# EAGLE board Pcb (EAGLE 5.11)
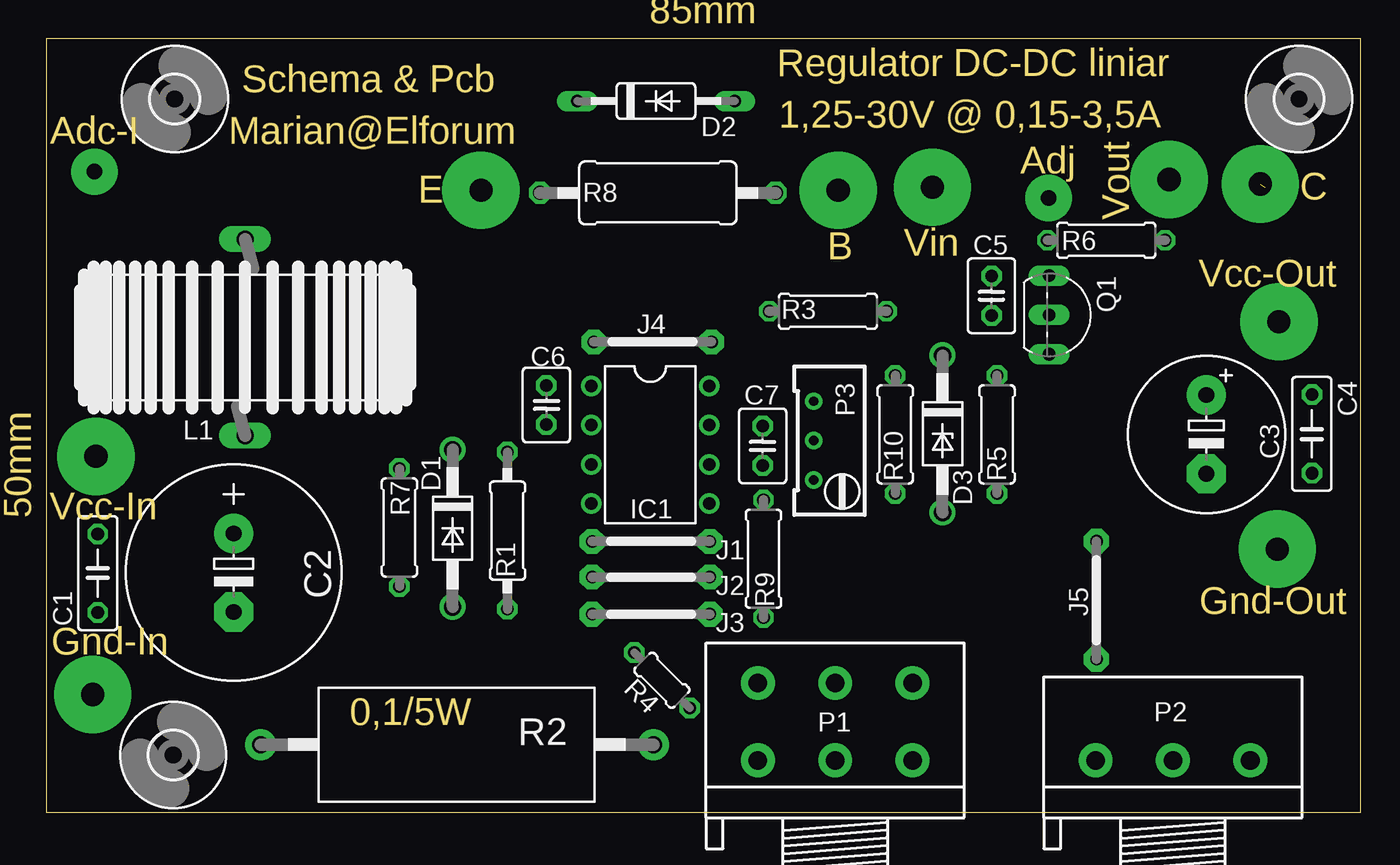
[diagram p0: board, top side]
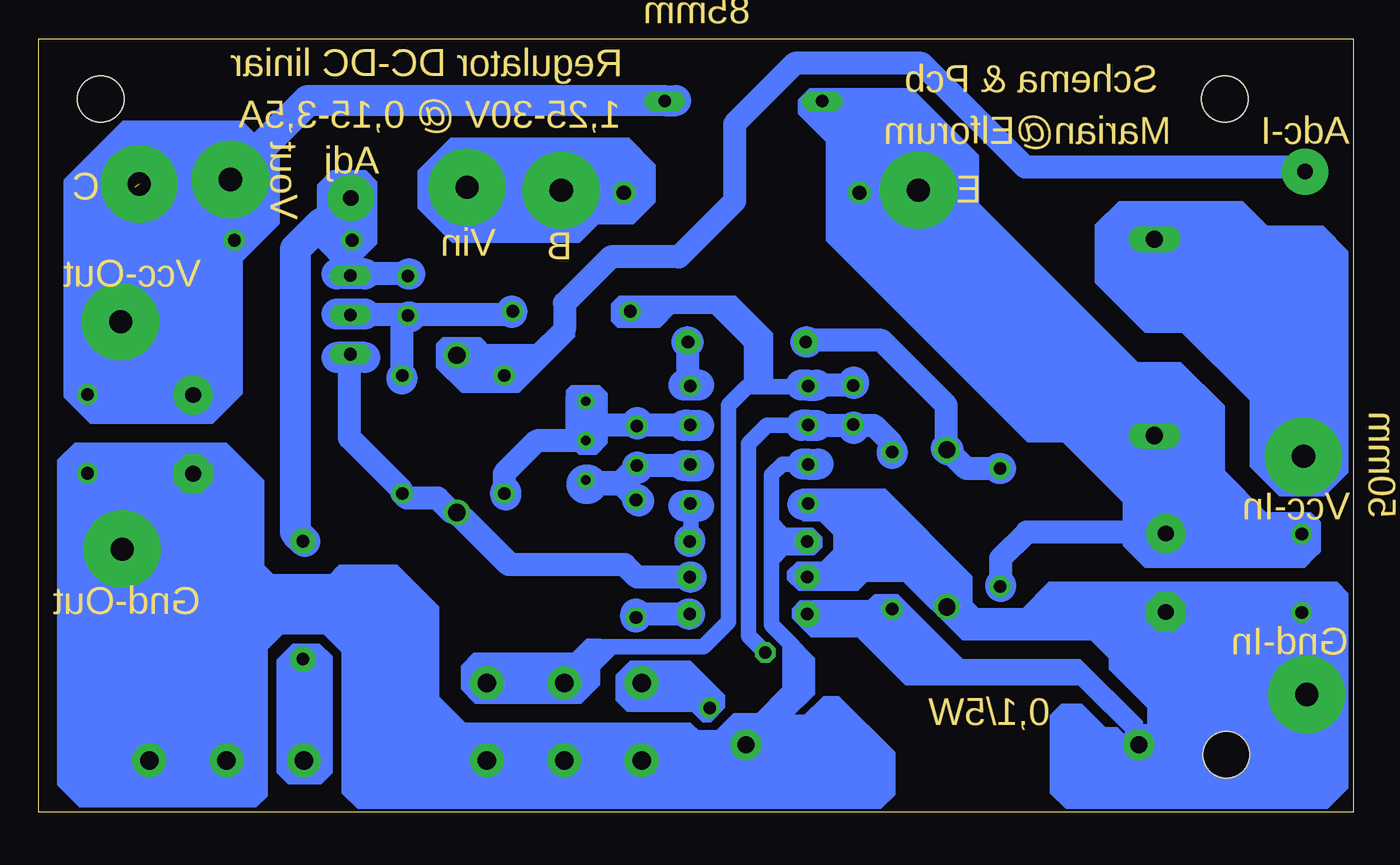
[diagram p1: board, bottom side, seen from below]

Size 85 x 50 mm. Coordinates in mm from the lower left corner, seen from the top.
Outline: 0,0 85,0 85,50 0,50 0,0
Copper layers (1*16): Top 0.035mm / dielectric 1.5mm / Bottom 0.035mm
Design rules "default": minimum track width 10mil, minimum drill 24mil, track to track 8mil, track to pad 8mil, pad to pad 8mil, via to via 8mil, smd to smd 8mil, copper to edge 40mil, drill to drill 8mil, minimum pad ring 10mil, minimum via ring 8mil, stop-mask expansion 4mil, vias tented up to drill 0mil, thermal gap 10mil

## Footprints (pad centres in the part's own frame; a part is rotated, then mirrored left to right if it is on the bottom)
C050-025X075 = drill 0.813 octagon: 1 -2.54,0; 2 2.54,0
E5-13 = drill 1.016 pad 2.54 round: + -2.54,0 | drill 1.016 pad 2.54 octagon: - 2.54,0
E5-10,5 = drill 1.016 pad 2.54 round: + -2.54,0 | drill 1.016 pad 2.54 octagon: - 2.54,0
C025-030X050 = drill 0.813 octagon: 1 -1.27,0; 2 1.27,0
DO41Z10 = drill 1.118 round: A 5.08,0; C -5.08,0
C2992 = drill 0.813 long: A 5.08,0; C -5.08,0
3,0 = hole 3: 0,0
DIL08 = drill 0.813 pad 1.27 round: 1 -3.81,-3.81; 2 -1.27,-3.81; 3 1.27,-3.81; 4 3.81,-3.81; 5 3.81,3.81; 6 1.27,3.81; 7 -1.27,3.81; 8 -3.81,3.81
07 = drill 0.813 pad 1.6 octagon: 1 -3.81,0; 2 3.81,0
SFT1030 = drill 1.118 long: 1 -6.35,0; 2 6.35,0
3RP/1610G = drill 1.2 pad 2.184 round: 1-1 -5,0; 1-2 0,0; 1-3 5,0; 2-1 -5,5; 2-2 0,5; 2-3 5,5
3RP/1610N = drill 1.2 pad 2.184 round: 1 -5,0; 2 0,0; 3 5,0
RTRIM64W = drill 0.61 round: 1 1.27,-2.54; 2 1.27,0; 3 1.27,2.54
TO92-EBC = drill 0.813 long: B 0,-1.27; C -2.54,-1.27; E 2.54,-1.27
0207/10 = drill 0.813 octagon: 1 -5.08,0; 2 5.08,0
AC05 = drill 1.1 pad 2 round: 1 -12.7,0; 2 12.7,0
0207/7 = drill 0.813 octagon: 1 -3.81,0; 2 3.81,0
0204/5 = drill 0.813 octagon: 1 -2.54,0; 2 2.54,0
0411/15 = drill 0.914 octagon: 1 -7.62,0; 2 7.62,0

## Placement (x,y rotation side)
C1  100n  [C050-025X075]  3.32,15.45 90 top
C2  1m  [E5-13]  12.11,15.48 270 top
C3  100u  [E5-10,5]  75.01,24.42 270 top
C4  100n  [C050-025X075]  81.83,24.45 270 top
C5  10n  [C025-030X050]  61.12,33.38 90 top
C6  10n  [C025-030X050]  32.33,26.32 270 top
C7  1n  [C025-030X050]  46.32,23.68 90 top
D1  15V  [DO41Z10]  26.27,18.35 270 top
D2  1N4007  [C2992]  39.42,45.97 0 top
D3  5V1  [DO41Z10]  57.95,24.45 270 top
E$1  [3,0]  8.3,46.1 0 top
E$2  [3,0]  81,46.1 0 top
E$3  [3,0]  8.2,3.7 0 top
IC1  LM358  [DIL08]  39.05,23.75 270 top
J1  [07]  39.1,17.5 0 top
J2  [07]  39.1,15.2 0 top
J3  [07]  39.1,12.8 0 top
J4  [07]  39.2,30.4 0 top
J5  [07]  67.9,13.7 90 top
L1  50uH  [SFT1030]  12.85,30.69 90 top
P1  50k  [3RP/1610G]  51.01,3.35 0 top
P2  10k  [3RP/1610N]  72.85,3.35 0 top
P3  10k  [RTRIM64W]  50.88,24.02 180 top
Q1  BC546A  [TO92-EBC]  66.12,32.14 270 top
R1  1k  [0207/10]  29.82,18.2 90 top
R2  0.1  [AC05]  26.55,4.36 180 top
R3  100  [0207/7]  50.54,32.38 0 top
R4  820  [0204/5]  39.8,8.53 135 top
R5  10k  [0207/7]  61.47,24.42 90 top
R6  430  [0207/7]  68.54,36.97 180 top
R7  1k  [0207/7]  22.83,18.4 270 top
R8  1  [0411/15]  39.54,40.03 0 top
R9  1k  [0207/7]  46.37,16.38 90 top
R10  430  [0207/7]  54.89,24.42 90 top

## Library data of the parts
C1-C7 P3 R1 R3-R10 = resistor
D1-D3 = diode
E$1-E$3 = holes
IC1 = linear
J1-J5 = jumper
L1 = inductors
P1 P2 = pot
Q1 = transistor-npn
R2 = resistor-power; OC_FARNELL: unknown; OC_NEWARK: unknown

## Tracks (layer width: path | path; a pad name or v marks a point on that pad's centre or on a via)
S$1
  Bottom 0.406: 37.7,11.8 36.7,10.8 36.7,8 38.5,6.2 40,6.2 41.1,5.1 42.4,5.1 42.9,5.6 57.5,5.6 59.3,7.4 59.3,13.2 61.9,15.8 65.5,15.8 66.1,15.2 69.9,15.2 70.6,15.9 70.6,21.4 72.9,23.7 82.6,23.7 83.6,22.7 83.6,1.8 82.3,0.5 71,0.5 70.4,1.1 70.4,10.6 69.3,11.7 66.5,11.7 65.2,10.4 65.2,1.3 64.3,0.4 30.6,0.4 29.8,1.2 29.8,3.8 33.3,7.3 34.2,7.3 35.4,6.1 36.6,6.1 35,7.7 35,9.9 36.3,11.2
S$2  (via drill 1.5 pad 5)
  other vias: 3.2,23
S$3
  Bottom 0.406: 2.7,20.6 3.2,20.6 4.7,20.6 6.5,22.4 6.5,26.7 11,31.2 13.4,31.2 16.5,34.3 16.5,37.9 15.1,39.3 7.2,39.3 5.6,37.7 2,37.7 0.5,36.2 0.5,22 1.9,20.6 2.7,20.6
S$4
  Bottom 1.5: 3.8,28.9 1.9,28.9 1.2,29.6 1.2,35.9 2.2,36.9 5.8,36.9 7.6,38.7 14.7,38.7 15.9,37.5 15.9,34.8 13.1,32 10.7,32 5.7,27 5.7,22.7 4.4,21.4 2.2,21.4 1.3,22.3 1.3,34.2 2.7,35.6 6.2,35.6 8.1,37.5 14.1,37.5 14.6,37 14.6,35.1 12.6,33.1 9.9,33.1 4.4,27.6 4.4,23.2 3.9,22.7 2.5,22.7 2.5,33.6 3.1,34.2 6.7,34.2 8.7,36.2 13.2,36.2 13.4,36.4 13.4,35.7 12.1,34.4 9.4,34.4 3.7,28.7 3.7,24 3.2,23.5
S$5
  Bottom 1.5: 3.5,29.3 3.5,32.8 3.8,33.1 7.1,33.1 9.2,35.2 11.9,35.2 12.1,35.4
S$6
  Bottom 0.406: 22.9,14.6 22.9,16.3 21.1,18.1 20.9,18.3 12.5,18.3 12.1,17.9
  Bottom 1.5: 22.8,14.7 22.8,16.4 21.1,18.1 12.7,18.1 12.6,18.2
  Bottom 2: 22.8,14.7 22.8,14.6
S$7
  Bottom 0.406: 12.4,17.8 12.2,18
S$8  (via drill 1.5 pad 5)
  other vias: 3,7.6
S$9
  Bottom 0.406: 26.3,23.5 26.3,26.4 30.2,30.3 35.4,30.3
  Bottom 1.5: 22.9,22.2 25,22.2 26.2,23.4 | 26.3,23.5 26.3,26.3 30.5,30.5 35.4,30.5 35.5,30.4
  Bottom 2: 22.8,22.2 22.9,22.2 | 26.2,23.4 26.3,23.5
S$10
  Bottom 1.5: 56.8,29.2 56.7,29.2 56.2,28.7 56.1,28.7 55.3,27.9 54.4,27.9 53.4,28.9
S$11  (via drill 1.5 pad 5)
  other vias: 79.6,17
S$12
  Bottom 0.406: 25.2,11.6 26.2,12.6
S$13
  Bottom 0.406: 30,13.1 29.9,13
S$14
  Bottom 0.406: 35.3,27.8 35.2,27.7
S$15  (via drill 1.5 pad 5)
  other vias: 79.7,31.7
S$16
  Bottom 0.406: 35.3,17.5 37.4,17.5
S$17
  Bottom 0.406: 35.3,25.1 35.4,25
S$18
  Bottom 0.406: 37.9,10.2 38.7,11 | 35.2,25 33,25 32.8,25.2 31.3,25.2 29.8,23.7 29.8,23.3
  Bottom 1: 35.2,25 37.9,25 39.1,23.8 39.1,11.4 37.9,10.2
  Bottom 1.5: 35.1,24.9 35,24.9 34.9,25 31,25 29.8,23.8 29.8,23.3
  Bottom 2: 34.7,25 34.9,25 35.2,25 35.7,25 | 29.8,23.3 29.8,23.2
S$19
  Bottom 0.406: 45.9,9.6 46.5,9.6 46.7,9.6 47.5,8.8 47.5,7.3 46.9,6.7 42.7,6.7 42,6 41.6,6 40.8,6.8 40.8,7.5 42.9,9.6 45.9,9.6
S$20
  Bottom 0.406: 46.3,22.3 46.3,22.4 46.3,22.5 43,22.5 42.8,22.7 | 46.3,22.2 46.3,20.2
  Bottom 1.5: 49.5,21.3 47.4,21.3 46.3,22.4 43.1,22.4
  Bottom 2: 42.3,22.4 43.1,22.4 43.3,22.4 | 46.3,22.3 46.3,22.2
S$21
  Bottom 1: 42.8,17.2 42.8,19.9
S$22
  Bottom 0.406: 32.4,27.6 35.3,27.6
  Bottom 1: 35.3,27.6 35.2,27.6
S$23
  Bottom 0.406: 13.9,4.5 14,4.5 14,4.7 17.7,8.4 28.9,8.4 32,11.5 35,11.5 36.1,12.6 36.1,13.1 35.7,13.5 31.3,13.5 30.9,13.9 29.5,13.9 25.3,9.7 17.7,9.7 13.8,5.8 13.8,4.6 13.7,4.6 | 13.7,4.6 14,4.3 | 13.7,4.6 13.1,5.2 13.1,6.8 15.6,9.3 15.6,10 16.9,11.3 25.2,11.3 29,15.1 31.5,15.1 32.1,14.5 35.8,14.5 36.4,15.1 36.4,15.5 35.9,16 34.3,16 33.4,16.9 33.4,18 34.4,19 35.5,19 36,19.5 36,20.3 35.6,20.7 30.3,20.7 24.8,15.2 24.8,13.5 24.3,13 21.3,13 19.6,14.7 1.1,14.7 0.5,14.1 0.5,1.6 1.7,0.4 18.5,0.4 19.4,1.3 19.4,6.2 18.8,6.8 17.6,6.8 16.1,5.3 15.3,5.3 14.3,4.3
S$24
  Bottom 0.406: 42.5,12.9 46.1,12.9 46.3,12.7 46.4,12.6 46.5,12.5
  Bottom 1.5: 43,12.8 46.2,12.8 46.3,12.7
  Bottom 2: 43,12.8 42.9,12.8 | 46.4,12.6 46.4,12.8
S$25
  Bottom 1.5: 64.9,32.2 54.7,32.2 54.5,32.4
  Bottom 2: 63.9,32.2 64.9,32.2 65.7,32.2
S$26
  Bottom 2: 63.9,34.8 65.7,34.8
S$27
  Bottom 1.5: 32.7,15.5 32.9,15.5 33.2,15.2 35.6,15.2 35.6,15.3 34.1,15.3 32.6,16.8 32.6,18.2 34,19.6 34,19.9 30.4,19.9 25.5,15 25.5,13.6 25.8,13.6 31,18.8 32.1,18.8 32.1,17.4 31.8,17.1 30.5,17.1 30.4,17 30.7,17 31.8,18.1
  Bottom 2: 14.8,2.2 14.8,3.4 15.7,4.3 16.6,4.3 18,5.7 18.3,5.7 18.4,5.8 18.4,1.7 18.1,1.4 2.2,1.4 1.5,2.1 1.5,13.6 1.6,13.7 19.2,13.7 20.8,12.1 24.7,12.1 28.6,16 32.2,16 32.7,15.5
S$28
  Bottom 0.406: 61.4,32.1 64.9,32.1 | 61.4,32.1 54.6,32.1 54.4,32.3 54.3,32.4 | 61.4,32.1 61.4,28
  Bottom 2: 54.4,32.4 54.4,32.3
S$29
  Bottom 0.406: 42.9,25 46.3,25 46.4,25 49.6,25 | 49.6,25 49.6,26.6 | 49.6,25 49.6,24.1
S$30
  Bottom 0.406: 49.7,21.6 47.3,21.6 46.5,22.4
S$31
  Bottom 1: 35.2,27.5 39.2,27.5 40.4,26.3 40.4,12.3 42,10.7 48.8,10.7
S$32
  Bottom 0.406: 42.4,10.4 49,10.4
S$33
  Bottom 0.406: 29.8,12.8 29.7,12.9
S$34
  Bottom 0.406: 54.8,28.1 56.6,28.1 58,29.5 58.1,29.6 | 54.9,28.3 53.2,28.3 51.1,30.4 51.1,33.3 48.5,35.9 48,35.9 | 40,39.5 40,43.9
  Bottom 1.5: 56.1,29.5 58,29.5 | 56.1,29.5 54.9,28.3 | 56.1,29.5 52.7,29.5 51,31.2 51,32.9 48,35.9 43.6,35.9 40,39.5 40,44.5 36.1,48.4 27.9,48.4 21.2,41.7 3.5,41.7 3.2,41.4
S$35
  Bottom 0.406: 58,19.4 57.1,19.4 53.8,16.1 46.9,16.1 45.7,14.9 43.1,14.9 42.8,15.2 | 58,19.4 58.1,19.4 | 64.9,24.2 64.9,23.9 61.5,20.5 59.1,20.5 58,19.4 | 64.9,29.5 64.9,29.6 | 58,19.4 57.7,19.1
  Bottom 1.5: 42.9,15.2 46.3,15.2 47.1,16 54.6,16 58,19.4 58.3,19.4 59.2,20.3 61.2,20.3 61.5,20.6 61.5,20.8 64.9,24.2 64.9,29.5
  Bottom 2: 42.9,15.2 42.8,15.2
S$36
  Bottom 0.406: 43.1,30.4 43.1,27.9 42.9,27.7 42.8,27.6
  Bottom 1.5: 43,30.5 43,30.4 43,27.8 42.9,27.7
  Bottom 2: 43,30.4 43.1,30.4
S$37
  Bottom 2: 63.9,29.4 65.7,29.4
S$38
  Bottom 0.406: 61.1,34.7 64.9,34.7
S$40  (via drill 1.5 pad 5)
  other vias: 57.3,40.4
S$41
  Bottom 0.406: 72.5,41.2 72.4,41.1
S$42
  Bottom 0.406: 48.7,11 49.5,11 50.4,10.1 56.8,10.1 57.5,9.4 57.5,8 56.7,7.2 50,7.2 48.9,8.3 48.9,9.3 47.7,10.5
S$43
  Bottom 0.406: 37.1,4.4 39,4.4
S$44
  Bottom 0.406: 73,40.7 68.6,45.1 67.7,46 44.6,46
S$45
  Bottom 0.406: 33.5,45.7 34.1,45.7
S$46
  Bottom 0.406: 13.2,24.7 13.2,24.5
S$47
  Bottom 0.406: 66.8,2 68.8,2 69.4,2.6 69.4,9.8 68.5,10.7 66.9,10.7 66.2,10 66.2,2.6 66.8,2
S$48
  Bottom 1.5: 20.3,12.4 20,12.1 16.6,12.1 14.8,10.3 14.8,9.7 12.4,7.3 12.4,4.9 14.1,3.2 15.1,3.2 15.7,3.8 17.3,3.8 17.4,3.9 17.4,3.1 17.2,2.9 16.2,2.9 16.1,2.8
S$49
  Bottom 3: 5.3,4.5 4.2,4.5 3.1,3.4 11.7,3.4 12.9,2.2 12.7,2.2 10.6,4.3 10.6,8 15,12.4 3.8,12.4 3.3,11.9 3.3,5.7 3,5.4 8.5,5.4 8.6,5.3 8.6,8.4 10.7,10.5 5.4,10.5 5.3,10.4 5.3,7.9 5,7.6 6.5,7.6 6.8,7.3 6.8,8.6 6.9,8.7 6.9,8.8
S$50
  Bottom 2: 43.8,46 44.5,46 67.6,46 72.3,41.3
S$51
  Bottom 0.406: 75.2,27 75.2,27.3
S$52
  Bottom 2: 75.3,33.9 73.2,33.9 72.9,33.6 72.9,27.7 74.3,26.3 81.3,26.3 82.3,27.3 82.3,40.2 79,43.5 72.3,43.5 70.5,41.7 70.5,38.7 73.3,35.9 73.3,35.8 73,35.5 73,29.8 74.9,27.9
S$53
  Bottom 0.406: 51.4,40.3 51.3,40.2
S$54
  Bottom 0.406: 51.7,40 51.6,40.1
S$55
  Bottom 1.5: 4.2,29.7 4.2,30.7 | 4.2,30.7 4.2,32 4.4,32.2 6,32.2 6.1,32.3 5.8,32.3 4.2,30.7
S$56
  Bottom 1: 35.3,22.5 36.9,22.5 37.6,21.8 37.6,12.1 36.2,10.7
  Bottom 2: 35.6,22.5 35.3,22.5 34.6,22.5
S$57  (via drill 1 pad 3)
  other vias: 3.1,41.4
S$58
  Bottom 1.5: 56.9,29.1 58.1,29.1 58.3,29.3 58.3,29.6 58.4,29.7 57.4,29.7 57.1,29.4
S$59
  Bottom 2: 34.6,19.9 35.6,19.9
S$60
  Bottom 1.5: 32.3,27.6 35.3,27.6
  Bottom 2: 34.7,27.6 35.3,27.6 35.7,27.6
S$61
  Bottom 2: 42.3,27.6 43.3,27.6
S$62
  Bottom 1.5: 42.9,25 49,25 49.2,25.2
  Bottom 2: 42.3,25 42.9,25 43.3,25
S$63
  Bottom 2: 42.3,19.8 43.3,19.8
S$64
  Bottom 0.406: 35.2,16.8 35.2,17.4 | 35.2,16.8 36.7,16.8 37.3,16.2 | 35.2,16.8 34.9,16.8 34.5,17.2 34.5,17.7 35,18.2 36.7,18.2 37.4,18.9
S$65  (via drill 1.5 pad 5)  (1 unrouted)
  other vias: 78.5,40.6
S$66
  Bottom 0.406: 38.4,4.3 38.6,4.3
S$67  (via drill 1.5 pad 5)
  other vias: 28.1,40.2
S$68  (via drill 1.5 pad 5)
  other vias: 51.2,40.2
S$69
  Bottom 1.5: 34.9,2.1 30.9,2.1 30.6,2.4 30.6,3.5 33.7,6.6 33.8,6.6 35.2,5.2 36.9,5.2 37.2,5.5 37.2,6.6 35.8,8 35.8,8.5 35.9,8.6 35.9,9.8 36,9.9
S$70
  Bottom 1.5: 37.5,4.3 37.5,6 37.6,6 38.4,5.2 38.4,5.4 39.7,5.4 40.8,4.3 42.8,4.3 43.3,4.8 57.9,4.8 60,6.9 60,12.7 62.4,15.1 65.1,15.1 65.9,14.3 70.1,14.3 71.6,15.8 71.3,15.8 71.2,15.9 71.2,20.9 73.2,22.9 82.2,22.9 82.8,22.3 82.8,2.1 82,1.3 71.4,1.3 71.2,1.5 71.2,11 69.6,12.6 69.3,12.6 69.2,12.5 66.2,12.5 64.4,10.7 64.4,1.6 63.9,1.1 31,1.1 30.5,1.6 30.5,1.7 33.7,4.9 33.7,4.8 34.3,4.2
S$71
  Bottom 3: 32.3,2.7 32.5,2.7 33.7,3.9 38.9,3.9 39.7,3.1 40.5,3.1 40.9,2.7 35.9,2.7 35.3,2.1
S$72
  Bottom 3: 41.1,3 62.8,3 62.9,2.9 62.9,11.8 64.3,13.2 71.9,13.2 72.9,12.2 72.9,3.2 72.5,2.8 80.8,2.8 81.1,3.1 81.1,21.3 81,21.4 73.9,21.4 72.8,20.3 72.8,15.3 72.4,14.9 74,14.9 75.4,13.5 75.4,5 75.3,4.9 78.7,4.9 78.7,18.8 78.8,18.9 75.4,18.9 75.3,19 75.3,16.9 75.6,16.6 75.9,16.6 76.8,17.5 76.8,6.6
S$73
  Bottom 3: 58.4,3.5 59,3.5 61,5.5 61,11.5 63.4,13.9
S$74
  Bottom 1.5: 67.5,4.7 67.1,4.7 67,4.8 67,9.6 67.3,9.9 67.6,9.9 | 68,9.9 68.3,9.9 68.7,9.5 68.7,3 68.4,2.7 67.3,2.7 66.9,3.1 66.9,9.2 67.6,9.9 | 68,9.9 67.6,9.9 | 68,9.9 68,3.1 67.9,3
S$75
  Bottom 1.5: 45.5,7.6 45.5,8.8 43.2,8.8 41.6,7.2 41.6,6.9 41.8,6.7 41.8,6.9 42.3,7.4 46.7,7.4 46.7,8.6 46.4,8.9
S$76
  Bottom 1.5: 55.4,8.8 55.4,9.2 55.3,9.3 50.1,9.3 49.2,10.2 48.9,10.2 48.8,10.3 48.9,10.3 49.7,9.5 49.7,8.5 50.3,7.9 56.4,7.9 56.8,8.3 56.8,9.2 56.6,9.4 55.7,9.4 55.6,9.3
S$77
  Bottom 1: 13.5,3.7 13.5,4.8 15,6.3 15.1,6.3 17.5,8.7 17.7,8.9 | 17.7,8.9 17.9,9.1 25.8,9.1 25.8,8.9 17.7,8.9
S$78
  Bottom 1: 25.4,9.2 25.5,9.2 29.7,13.4 30.7,13.4 31,13.1 35.3,13.1 35.6,12.8 35.6,12.7 34.9,12 31.7,12 28.6,8.9 26.6,8.9 26.5,8.8 26.5,9.1 30.2,12.8 34.7,12.8 | 34.7,12.8 35.2,12.8 | 34.7,12.8 34.3,12.4 30.4,12.4 27.6,9.6 28.3,9.6 28.4,9.5 31.1,12.2
S$79
  Bottom 1: 14.1,4.9 14.1,4.8 14.4,4.5
S$80
  Bottom 1: 14.2,5.1 14.2,5 14.7,4.5
S$81
  Bottom 1: 12.8,5.2 13.9,5.2 14,5.1
S$82
  Bottom 1: 37.3,18.2 37.3,18 37,17.7 35.2,17.7 35,17.5 35,17.3 36.9,17.3 37.3,16.9
S$83
  Bottom 0.406: 2.4,16.8 2.4,18.6 | 2.4,16.8 2.6,16.6 3.2,16 13.4,16 14.7,17.3 14.7,20.1 18.7,24.1 21,24.1 33.9,37 33.9,43.4 35.7,45.2 35.7,46 35.1,46.6 28.6,46.6 24.4,42.4 24.4,39.3 14,28.9 11.2,28.9 8.5,26.2 8.5,22 5.7,19.2 2.8,19.2 2.3,18.7 2.3,16.9 2.4,16.8
S$84
  Bottom 1.5: 5.5,17.4 5.5,17.7 5.5,18.4 5.4,18.5 3.3,18.5 3.1,18.3 3.1,18 | 3.1,18 3.1,17.1 3.5,16.7 13,16.7 14.1,17.8 14.1,20.6 18.4,24.9 20.8,24.9 33.1,37.2 33.1,43.7 34.8,45.4 34.8,45.8 34.7,45.9 28.9,45.9 25.2,42.2 25.2,38.9 14.6,28.3 14.4,28.3 14.1,28 11.4,28 9.2,25.8 9.2,21.5 6.4,18.7 6.3,18.7 6.1,18.5 3.6,18.5 3.1,18 | 3.1,18 4.9,18 5.1,17.8
  Bottom 3: 5.5,17.7 11.7,17.7 12.9,18.9 12.9,21.5 18.2,26.8 20.2,26.8 31.7,38.3 31.7,43.5 32.7,44.5 29.7,44.5 26.7,41.5 26.7,38.1 15.6,27 12.6,27 10.8,25.2 10.8,21.1 8.4,18.7 10.3,18.7 10.9,19.3 10.9,22 14.3,25.4
S$85
  Bottom 3: 18.5,27.5 18.5,28.1 29.6,39.2 29.6,41.8 30.2,42.4 30.2,42.1 27.9,39.8
S$86
  Bottom 0.406: 37.7,27.4 37.7,30.9 40,33.2 47.4,33.2 47.8,32.8 47.8,31.8 47.5,31.5 44.9,31.5 44,32.4 | 44,32.4 46.8,32.4 | 39.2,30.2 38.6,29.6 | 44,32.4 41.4,32.4 39.2,30.2 | 39.2,30.2 39.2,27.1
S$87
  Bottom 1: 38.6,28.2 38.2,28.2 38.2,30.5 40.3,32.6 40.9,32.6 41.1,32.8 44.4,32.8 45.2,32 47.2,32 47.3,32.1 47.3,32.7 47.2,32.8 44.9,32.8
S$88
  Bottom 1: 38.3,27.9 38.3,28.1 38.8,28.6 38.8,30.4 40.9,32.5
S$89
  Bottom 2: 32.3,24.9 32.3,24.8
S$90
  Bottom 2: 32.3,27.7 32.3,27.8
S$91
  Bottom 2: 35.3,30.4 35.4,30.4
S$92
  Bottom 0.406: 21.3,41.4 21.4,41.4 | 21.3,41.4 27.5,47.6 | 21.3,41.4 3.3,41.4 3.2,41.3
S$93
  Bottom 0.406: 55.3,27.3 55.3,27.5 | 55.3,27.3 54.9,27.3 | 54.9,27.3 54,27.3 50.5,30.8 50.5,31.6 | 54.9,27.3 54.9,27.5 | 55.3,27.3 57.6,27.3 59.1,28.8 59.1,30.2 58.8,30.5 56.5,30.5 55.9,29.9
S$94
  Bottom 0.406: 57.2,30.2 56.7,30.2 56.6,30.1
S$95
  Bottom 0.406: 56,28.2 56,27.6 57.6,27.6 57.9,27.9 57.9,28 | 57.9,28 58.4,28.5 57.7,28.5 | 57.7,28.5 57.4,28.5 57.1,28.2 56.6,28.2 56.2,27.8 57.7,27.8 57.9,28 | 57.7,28.5 57.1,27.9 57.6,27.9 57.7,28 57.7,28.1 58,28.4 58.4,28.4
S$96
  Bottom 0.406: 54.9,20.7 54.9,21.3 52.2,24 50.7,24 | 50.7,24 49.6,24 | 50.7,24 50,23.3 49,23.3 48.4,23.9 48.4,27 48.8,27.4 50.5,27.4 50.7,27.2 50.7,24
S$97
  Bottom 1.5: 54.9,20.6 54.9,21.9 52.8,24 49.6,24 49.5,24.1 49.1,24.1 49.1,26.6 49.2,26.7 50.2,26.7 50.2,24.5 50,24.3
S$98
  Bottom 1.5: 49.5,21.2 47.3,21.2 46.3,20.2
  Bottom 2: 46.3,20.2 46.2,20.1
  Bottom 2.54: 49.5,21.2 49.6,21.2
S$99
  Bottom 2: 54.8,20.5 54.8,20.7
S$100
  Bottom 2: 46.3,25.2 46.3,25.1
S$101
  Bottom 2: 42.9,17.6 42.9,17.5
S$102
  Bottom 0.406: 45.3,41.2 45.3,41.1 45.3,39.5 46.6,38.2 48.9,38.2 50.1,37 58.2,37 60.3,39.1 60.3,41.4 58.3,43.4 46.9,43.4 45.3,41.8 45.3,41.2
S$103
  Bottom 0.406: 64.6,35.5 63.3,36.8 63.3,40.7 63.9,41.3 66,41.3 66.8,40.5 66.8,36.6 65.5,35.3
S$104
  Bottom 2: 66.4,38.1 66.7,38.1 68.4,36.4 68.4,18.1 67.8,17.5
S$105
  Bottom 0.406: 69.6,40.9 69.6,40.5 69.6,38.1 72,35.7 72,27.1 73.8,25.3 81.6,25.3 83.2,26.9 83.2,40.8 79.5,44.5 71.9,44.5 69.6,42.2 69.6,40.9
S$106  (via drill 1.5 pad 5)
  Bottom 0.406: 73.1,40.4 v72.6,40.9
S$107
  Bottom 3: 75.3,28.1 80.1,28.1 80.1,39.4 78,41.5 72,41.5 71.9,41.4 71.9,40.4 75,37.3 75,30.4 75.2,30.2 77.4,30.2 77.6,30.4 77.6,38.8 77.3,39.1 75,39.1 74.4,39.7
S$108  (via drill 1 pad 3)
  Bottom 0.406: 64.8,39.6 v64.8,39.7 | 64.8,39.6 64.8,36.5 64.8,34.7 64.9,34.6 | 67.9,17.6 67.9,36.5 64.8,39.6
  Bottom 1.5: 65.4,36.9 64.4,36.9 64.1,37.2 64.1,40.3 64.3,40.5 65.8,40.5 66.1,40.2 66.1,36.9 65.7,36.5 65,36.5 | 64.8,36.5 65,36.5 | 65,36.5 65.1,36.6 65.1,40.3 65,40.4
S$109
  Bottom 1.5: 55.3,41.3 55.3,42.5 55.2,42.6 47,42.6 46,41.6 46,39.8 46.9,38.9 49.3,38.9 50.5,37.7 57.9,37.7 59.6,39.4 59.6,41 58,42.6 55.5,42.6 55.4,42.7
S$110
  Bottom 3: 55.3,41 47.7,41 47.5,40.8 47.5,40.4 47.7,40.2 50.3,40.2 51.3,39.2 57.6,39.2 58.2,39.8 58.2,39.9 56.9,41.2 56.6,41.2 55.3,39.9 50,39.9 49.4,40.5
S$111
  Bottom 1.5: 61.5,28.2 61.5,32
S$112
  Bottom 2: 61.5,28.1 61.5,28
S$113
  Bottom 2: 61.1,32 61,32
S$114
  Bottom 1.5: 61.1,34.8 63.7,34.8 63.8,34.9
  Bottom 2: 61,34.8 61.1,34.8

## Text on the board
Dimension: 85mm | Regulator DC-DC liniar | Schema & Pcb | 1,25-30V @ 0,15-3,5A | Adc-I | Marian@Elforum | Adj | C | E | Vout | B | Vin | Vcc-Out | 50mm | Vcc-In | Gnd-Out | Gnd-In | 0,1/5W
